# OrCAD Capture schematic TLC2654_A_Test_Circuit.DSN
size A; title: TLC2654, TLC2654A Advanced LinCMOS LOW-NOISE; rev: 1.1; note: Datasheet: SLOS020G EVM: N/A
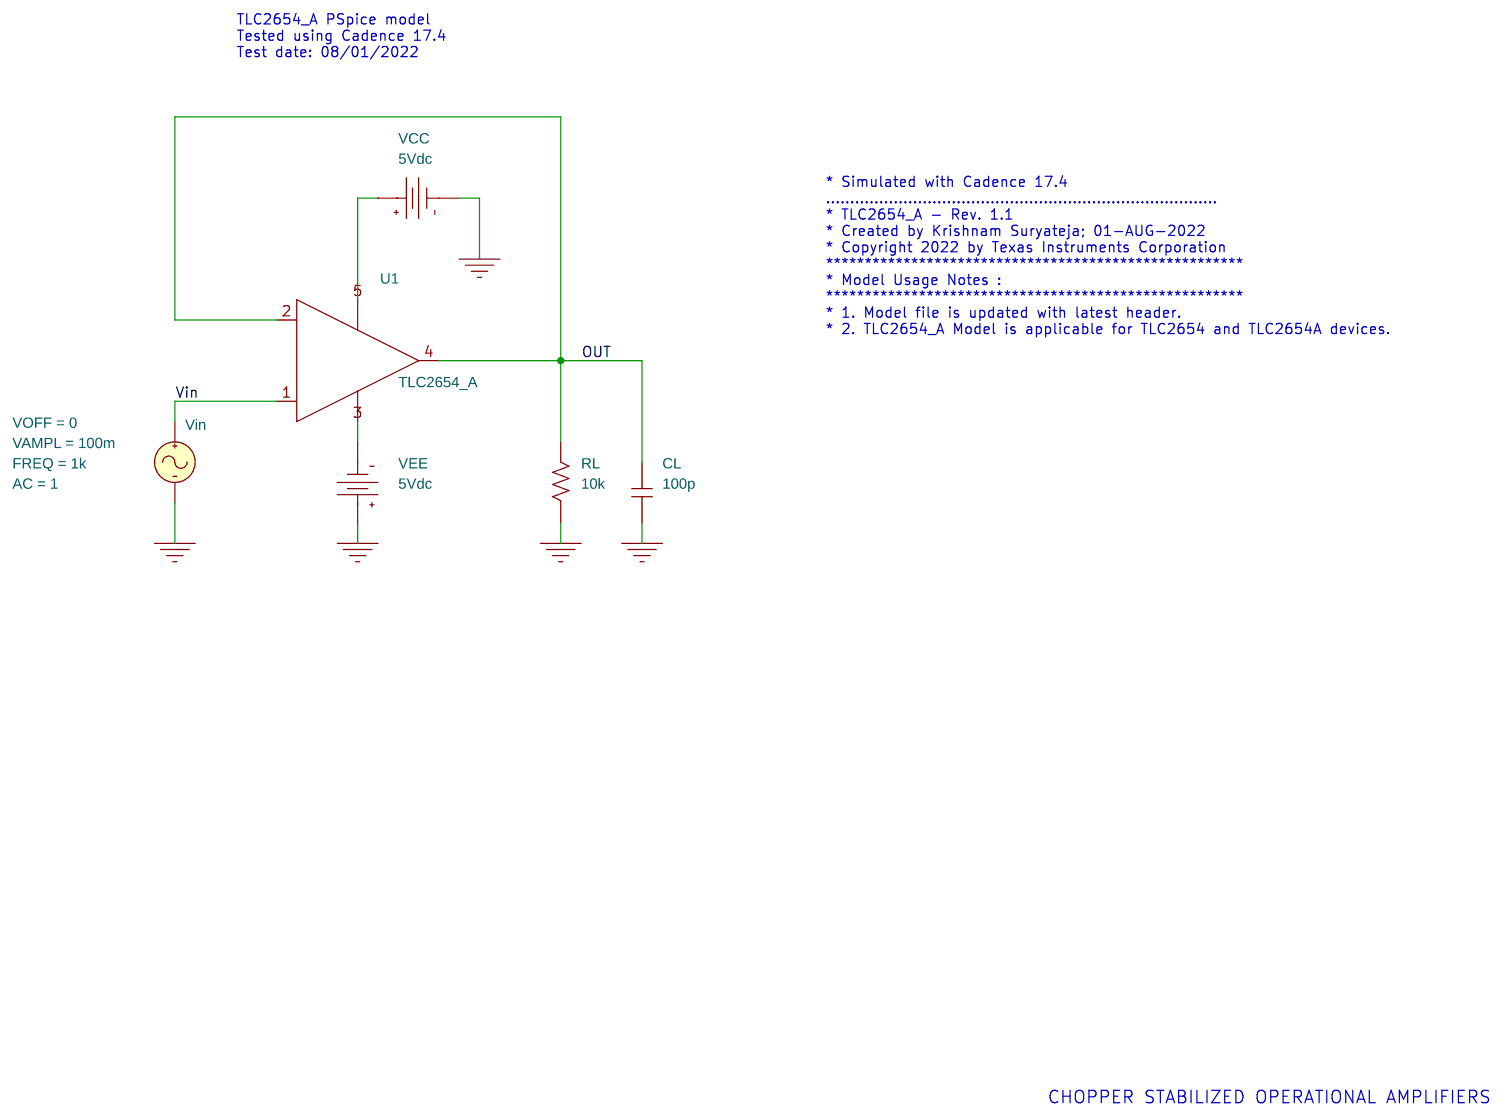
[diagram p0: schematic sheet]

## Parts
CL  100p  [RAD/CK05]
RL  10k  [AX/RC05]
U1  TLC2654_A
VCC  VDC
VEE  VDC
Vin  VSIN

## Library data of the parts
CL = C
RL = R
U1 = TLC2654_A
VCC VEE = VDC: DC: 5Vdc
Vin = VSIN: AC: 1; FREQ: 1k; VAMPL: 100m; VOFF: 0

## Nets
Vin: U1.1(+) Vin.1(+)
0: CL.1 RL.1 VCC.1(-) VEE.0(+) Vin.2(-)
OUT: CL.2 RL.2 U1.2(-) U1.4(OUT)
N22995: U1.5(V+) VCC.0(+)
N23017: U1.3(V-) VEE.1(-)

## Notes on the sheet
- TLC2654_A PSpice model
  Tested using Cadence 17.4
  Test date: 08/01/2022
- * Simulated with Cadence 17.4
  .................................................................................
  * TLC2654_A - Rev. 1.1
  * Created by Krishnam Suryateja; 01-AUG-2022
  * Copyright 2022 by Texas Instruments Corporation
  ******************************************************
  * Model Usage Notes :
  ******************************************************
  * 1. Model file is updated with latest header.
  * 2. TLC2654_A Model is applicable for TLC2654 and TLC2654A devices.
- CHOPPER STABILIZED OPERATIONAL AMPLIFIERS
